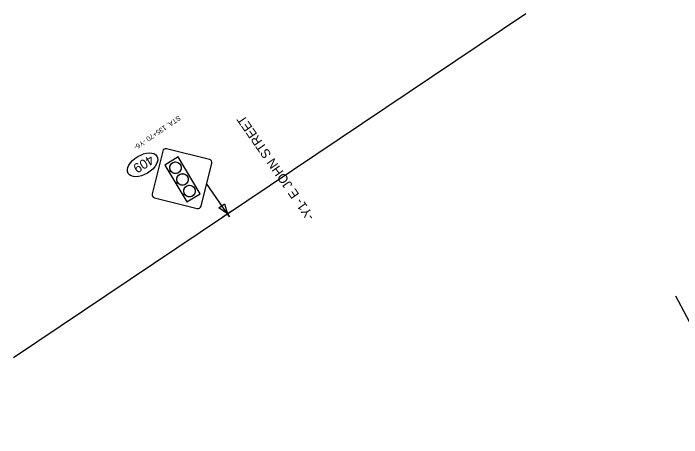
# Model space of a CAD drawing. Extents: x 1487362 to 2061618, y 497428 to 671257.
# Drawn here: x 1487361.7 to 1487794.9, y 498499.5 to 498774.3 of the extents above; entities that cross this region are included whole.
import ezdxf

# ---------------------------------------------------------------- set-up
doc = ezdxf.new("R2010")
doc.units = 0
for name, color, linetype in [('Prop Horizontal Alignment Direction Label', 7, 'Continuous'), ('Prop Sign E Signal Light Ahead CELL', 7, 'Continuous'), ('Prop Support One', 7, 'Continuous'), ('Scratch_Level_1', 7, 'Continuous'), ('Text', 7, 'Continuous')]:
    doc.layers.add(name, color=color, linetype=linetype)

msp = doc.modelspace()

# ---------------------------------------------------------------- linework, layer by layer
at = {"layer": 'Prop Sign E Signal Light Ahead CELL'}
for p, q in [((1487458.56, 498685.12), (1487451.65, 498657.36)), ((1487488.8, 498679.7), (1487461.04, 498686.61)), ((1487483.38, 498649.46), (1487490.29, 498677.22)), ((1487463.61, 498672.39), (1487463.61, 498672.39)), ((1487463.61, 498672.39), (1487463.61, 498672.39)), ((1487453.14, 498654.88), (1487480.91, 498647.97))]:
    msp.add_line(p, q, dxfattribs=at)
msp.add_lwpolyline([(1487468.55, 498681.28), (1487459.86, 498676.05), (1487474.17, 498652.25), (1487482.86, 498657.48)], close=True, dxfattribs=at)
for points in [[(1487472.69, 498657.28), (1487471.56, 498656.59), (1487474.17, 498652.25), (1487482.86, 498657.48), (1487468.55, 498681.28), (1487459.86, 498676.05), (1487462.47, 498671.71), (1487463.61, 498672.39)], [(1487472.69, 498657.28), (1487471.56, 498656.59), (1487474.17, 498652.25), (1487482.86, 498657.48), (1487468.55, 498681.28), (1487459.86, 498676.05), (1487462.47, 498671.71), (1487463.61, 498672.39)], [(1487463.61, 498672.39), (1487462.47, 498671.71), (1487467.02, 498664.15), (1487468.15, 498664.83)], [(1487463.61, 498672.39), (1487462.47, 498671.71), (1487467.02, 498664.15), (1487468.15, 498664.83)], [(1487468.15, 498664.83), (1487467.02, 498664.15), (1487471.56, 498656.59), (1487472.69, 498657.28)], [(1487468.15, 498664.83), (1487467.02, 498664.15), (1487471.56, 498656.59), (1487472.69, 498657.28)]]:
    msp.add_lwpolyline(points, dxfattribs=at)
for centre in [(1487466.82, 498674.32), (1487466.82, 498674.32), (1487471.36, 498666.76), (1487471.36, 498666.76), (1487475.9, 498659.21), (1487475.9, 498659.21)]:
    msp.add_circle(centre, 3.75, dxfattribs=at)
for centre, radius, start, end in [((1487460.54, 498684.63), 2.04, 76.022, 166.022), ((1487488.31, 498677.72), 2.04, 346.022, 76.022), ((1487466.82, 498674.32), 3.75, 211.0273, 211.022), ((1487466.82, 498674.32), 3.75, 211.0273, 211.022), ((1487471.36, 498666.76), 3.75, 211.0273, 211.022), ((1487471.36, 498666.76), 3.75, 211.0273, 211.022), ((1487475.9, 498659.21), 3.75, 211.0273, 211.022), ((1487475.9, 498659.21), 3.75, 211.0273, 211.022), ((1487453.63, 498656.86), 2.04, 166.022, 256.022), ((1487481.4, 498649.95), 2.04, 256.022, 346.022)]:
    msp.add_arc(centre, radius, start, end, dxfattribs=at)
msp.add_ellipse((1487445.49, 498676.22), major_axis=(9.31, 5.59), ratio=0.571429, dxfattribs=at)
at = {"layer": 'Prop Support One'}
for p, q in [((1487501.74, 498642.61), (1487487.01, 498664.07)), ((1487494.88, 498648.34), (1487498.65, 498650.93)), ((1487498.65, 498650.93), (1487500.43, 498644.51)), ((1487500.43, 498644.51), (1487494.88, 498648.34)), ((1487497.6, 498642.57), (1487503.21, 498646.42)), ((1487500.43, 498644.51), (1487501.74, 498642.61))]:
    msp.add_line(p, q, dxfattribs=at)
at = {"layer": 'Scratch_Level_1'}
for p, q in [((1487361.71, 498551.45), (1487693.88, 498774.3)), ((1487978.37, 498237.53), (1487791.23, 498591.05))]:
    msp.add_line(p, q, dxfattribs=at)

# ---------------------------------------------------------------- texts
at = {"layer": 'Prop Horizontal Alignment Direction Label'}
msp.add_text('-Y1- E JOHN STREET', height=6, rotation=124.8687, dxfattribs=at).set_placement((1487557.25, 498642.72))
at = {"layer": 'Prop Sign E Signal Light Ahead CELL'}
msp.add_text('409', height=6.132, rotation=210.9879, dxfattribs=at).set_placement((1487450.49, 498682.81))
at = {"layer": 'Text'}
msp.add_text('STA. 135+70 -Y6-', height=3.2, rotation=214.361, dxfattribs=at).set_placement((1487468.79, 498708.31))

doc.saveas('drawing.dxf')
